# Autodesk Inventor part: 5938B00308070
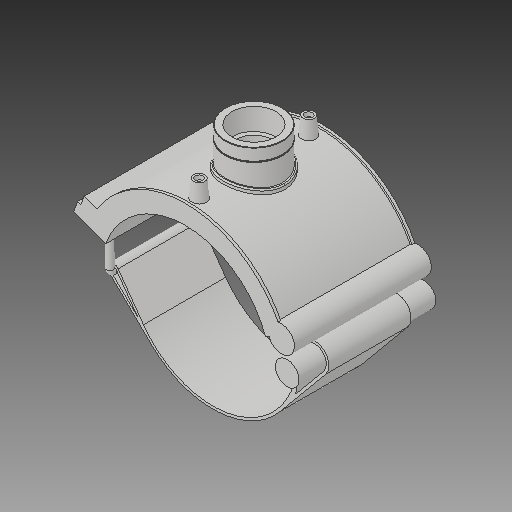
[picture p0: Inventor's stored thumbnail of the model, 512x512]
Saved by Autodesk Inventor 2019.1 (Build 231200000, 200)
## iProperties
Created: 2017-07
Part Number: 5938B00308070
Material: Generic
Description: PLASSON TRANSITION SADDLE 8''IPS x 2"NPT
Document SubType Name: Modeling
Designer: KIM
Density: 1 g/cm^3
Appearance: Default
Author: KIM
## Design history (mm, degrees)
derived "5938B.ipt"
feature "Solid1::5938B.ipt"
tag "TaggingFeature1"
body "Solid1"
other parameters: "d0" = 218.7, "d1" = 262.44, "d2" = 449.58, "d3" = 54.675, "d4" = 176.022, "d5" = 0, "d40" = 136.4688, "d41" = 79.3184, "d43" = 0, "d45" = 0, "d47" = 177.956, "d48" = 73.6528, "d50" = 0, "d78" = 153.22, "d79" = 15, "d80" = 70.4088, "d82" = 5 deg, "d84" = 4, "d85" = 14, "d86" = 0, "d87" = 3, "d88" = 0, "d96" = 267.6888, "d97" = 3.52044, "d98" = 0, "d102" = 1.69968, "d103" = 56.656, "d104" = 28.0416, "d105" = 0, "d106" = 45.3248, "d108" = 0, "d109" = -15.57867, "d111" = 0.5, "d112" = 0.5, "d113" = 0, "d114" = 0.5, "d117" = 0.56656, "d120" = 140 deg, "d121" = 24.228, "d122" = 20 deg, "d123" = 1049.76, "d124" = 157.464, "d126" = 0, "d143" = 225.261, "d145" = 33.64615, "d149" = 3.2805, "d150" = 37.01077, "d153" = 176.022, "d154" = 0, "d156" = 131.22, "d157" = 160 deg, "d159" = 8.748, "d161" = 3.2805, "d162" = 105.6132, "d163" = 0, "d164" = 109.35, "d167" = 21.87, "d168" = 128.01951, "d170" = 3.2805, "d172" = 0, "d173" = 1, "d175" = 109.35, "d176" = 20 deg, "d177" = 15.309, "d178" = 43.74, "d180" = 0, "d183" = 17.496, "d184" = 12.2472, "d185" = 57.20715, "d186" = 57.20715, "d187" = 131.22, "d188" = 13.122, "d189" = 15.309, "d190" = 0, "d191" = 157.464, "d193" = 8.748, "d194" = 4.48335, "d195" = 90 deg, "d197" = 0, "d199" = 0, "d_" = 218.7, "B_" = 179.832, "H_" = 46.736, "L_" = 176.022, "d_t" = 6, "G_" = 56.656, "d148" = 3.2805, "d160" = 3.2805, "d169" = 3.2805, "d192" = 8.748
